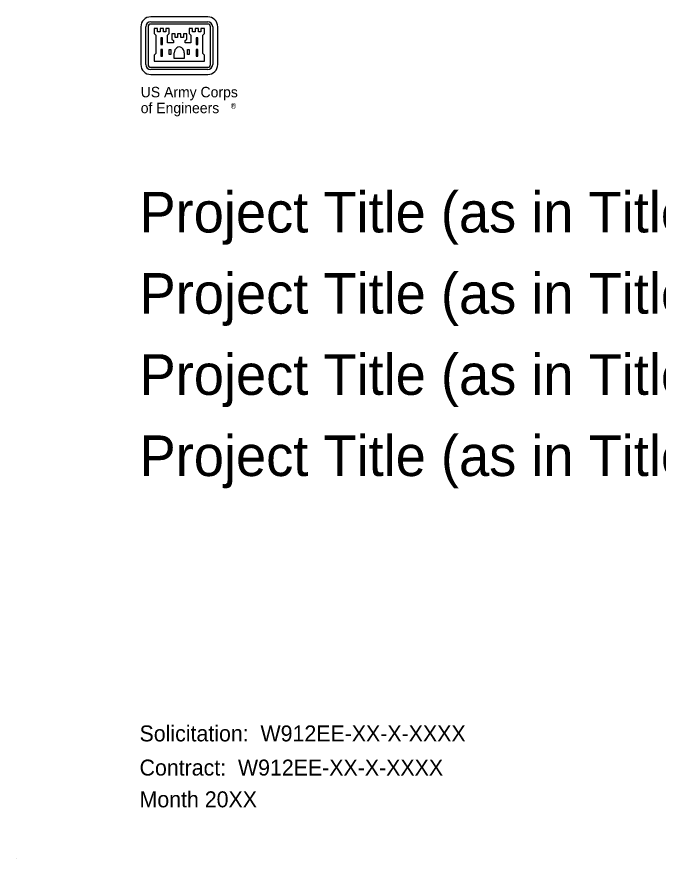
# Model space of a CAD drawing. Extents: x 0 to 2.77, y 0 to 1.73.
# Drawn here: x 0 to 1.318, y 0 to 1.727 of the extents above; entities that cross this region are included whole.
import ezdxf

# ---------------------------------------------------------------- set-up
doc = ezdxf.new("R2010")
doc.units = 0
for name, color, linetype in [('G-ANNO-SYMB', 7, 'Continuous'), ('G-ANNO-TEXT', 7, 'Continuous'), ('G-ANNO-TEXT-PROJ', 7, 'Continuous')]:
    doc.layers.add(name, color=color, linetype=linetype)

msp = doc.modelspace()

# ---------------------------------------------------------------- linework, layer by layer
at = {"layer": 'G-ANNO-SYMB'}
for p, q in [((0.3922, 1.7272), (0.2755, 1.7272)), ((0.2755, 1.7272), (0.2755, 1.7272)), ((0.2755, 1.7169), (0.3922, 1.7169)), ((0.3922, 1.7124), (0.2755, 1.7124)), ((0.3922, 1.7124), (0.3922, 1.7124)), ((0.2549, 1.7066), (0.2549, 1.6294)), ((0.2651, 1.6294), (0.2651, 1.7066)), ((0.2651, 1.7066), (0.2651, 1.7066)), ((0.2697, 1.7066), (0.2697, 1.6294)), ((0.3979, 1.6294), (0.3979, 1.7066)), ((0.4025, 1.7066), (0.4025, 1.6294)), ((0.4128, 1.6294), (0.4128, 1.7066)), ((0.3235, 1.6414), (0.3235, 1.653)), ((0.3441, 1.6414), (0.3235, 1.6414)), ((0.3441, 1.653), (0.3441, 1.6414)), ((0.2755, 1.6236), (0.3922, 1.6236)), ((0.3922, 1.6191), (0.2755, 1.6191)), ((0.2755, 1.6088), (0.3922, 1.6088))]:
    msp.add_line(p, q, dxfattribs=at)
for points in [[(0.2823, 1.7032), (0.2823, 1.6929), (0.2857, 1.6895), (0.2857, 1.6517), (0.2823, 1.6483), (0.2823, 1.6363), (0.3853, 1.6363), (0.3853, 1.6483), (0.3819, 1.6517), (0.3819, 1.6895), (0.3853, 1.6929), (0.3853, 1.7032), (0.3784, 1.7032), (0.3784, 1.6963), (0.3733, 1.6963), (0.3733, 1.7032), (0.3664, 1.7032), (0.3664, 1.6963), (0.3613, 1.6963), (0.3613, 1.7032), (0.3544, 1.7032), (0.3544, 1.6929), (0.3578, 1.6895), (0.3578, 1.6741), (0.3458, 1.6741), (0.3458, 1.6783), (0.3492, 1.6817), (0.3492, 1.692), (0.3424, 1.692), (0.3424, 1.6851), (0.3372, 1.6851), (0.3372, 1.692), (0.3304, 1.692), (0.3304, 1.6851), (0.3252, 1.6851), (0.3252, 1.692), (0.3184, 1.692), (0.3184, 1.6817), (0.3218, 1.6783), (0.3218, 1.6741), (0.3098, 1.6741), (0.3098, 1.6895), (0.3132, 1.6929), (0.3132, 1.7032), (0.3063, 1.7032), (0.3063, 1.6963), (0.3012, 1.6963), (0.3012, 1.7032), (0.2943, 1.7032), (0.2943, 1.6963), (0.2892, 1.6963), (0.2892, 1.7032), (0.2823, 1.7032)], [(0.296, 1.6706), (0.2995, 1.6706), (0.2995, 1.6843), (0.296, 1.6843), (0.296, 1.6706)], [(0.3682, 1.6842), (0.3683, 1.6843)], [(0.3682, 1.6706), (0.3716, 1.6706), (0.3716, 1.6843), (0.3682, 1.6843), (0.3682, 1.6706)], [(0.296, 1.6465), (0.2995, 1.6465), (0.2995, 1.6603), (0.296, 1.6603), (0.296, 1.6465)], [(0.3132, 1.6603), (0.3166, 1.6603), (0.3166, 1.65), (0.3132, 1.65), (0.3132, 1.6603)], [(0.351, 1.6603), (0.3544, 1.6603), (0.3544, 1.65), (0.351, 1.65), (0.351, 1.6603)], [(0.3682, 1.6465), (0.3716, 1.6465), (0.3716, 1.6603), (0.3682, 1.6603), (0.3682, 1.6465)], [(0.3714, 1.6706), (0.3716, 1.6707)]]:
    msp.add_lwpolyline(points, dxfattribs=at)
for centre, radius, start, end in [((0.2754, 1.7066), 0.0206, 90, 180), ((0.2754, 1.7066), 0.0103, 90, 180), ((0.2754, 1.7066), 0.00578, 90, 180), ((0.3922, 1.7066), 0.0206, 0, 90), ((0.3922, 1.7066), 0.0103, 0, 90), ((0.3922, 1.7066), 0.00578, 0, 90), ((0.2754, 1.6294), 0.0206, 180, 270), ((0.2754, 1.6294), 0.0103, 180, 270), ((0.2754, 1.6294), 0.00578, 180, 270), ((0.3922, 1.6294), 0.0206, 270, 360), ((0.3922, 1.6294), 0.0103, 270, 360), ((0.3922, 1.6294), 0.00578, 270, 360)]:
    msp.add_arc(centre, radius, start, end, dxfattribs=at)
msp.add_ellipse((0.3338, 1.653), major_axis=(0, 0.0124), ratio=0.827815, start_param=4.712389, end_param=7.853982, dxfattribs=at)
at = {"layer": 'G-ANNO-TEXT'}
msp.add_line((0, 0), (0, 0), dxfattribs=at)
msp.add_line((0, 0), (0, 0), dxfattribs=at)
msp.add_line((0, 0), (0, 0), dxfattribs=at)
msp.add_line((0, 0), (0, 0), dxfattribs=at)

# ---------------------------------------------------------------- texts
at = {"layer": 'G-ANNO-SYMB'}
for s, height, p in [('US Army Corps', 0.021484, (0.2546, 1.562)), ('US Army Corps', 0.021484, (0.2546, 1.562)), ('of Engineers', 0.021484, (0.2546, 1.5294)), ('of Engineers', 0.021484, (0.2546, 1.5294)), ('®', 0.0115, (0.4396, 1.5389))]:
    msp.add_text(s, height=height, dxfattribs=at).set_placement(p)
at = {"layer": 'G-ANNO-TEXT-PROJ'}
for s, height, p in [('Project Title (as in Title Block)', 0.083333, (0.252, 1.2845)), ('Project Title (as in Title Block)', 0.083333, (0.2522, 1.1178)), ('Project Title (as in Title Block)', 0.083333, (0.2522, 0.9512)), ('Project Title (as in Title Block)', 0.083333, (0.2522, 0.7845)), ('Solicitation:  W912EE-XX-X-XXXX', 0.032782, (0.2522, 0.2397)), ('Contract:  W912EE-XX-X-XXXX', 0.032782, (0.2522, 0.1696)), ('Month 20XX', 0.03278, (0.2522, 0.1044))]:
    msp.add_text(s, height=height, dxfattribs=at).set_placement(p)

doc.saveas('drawing.dxf')
